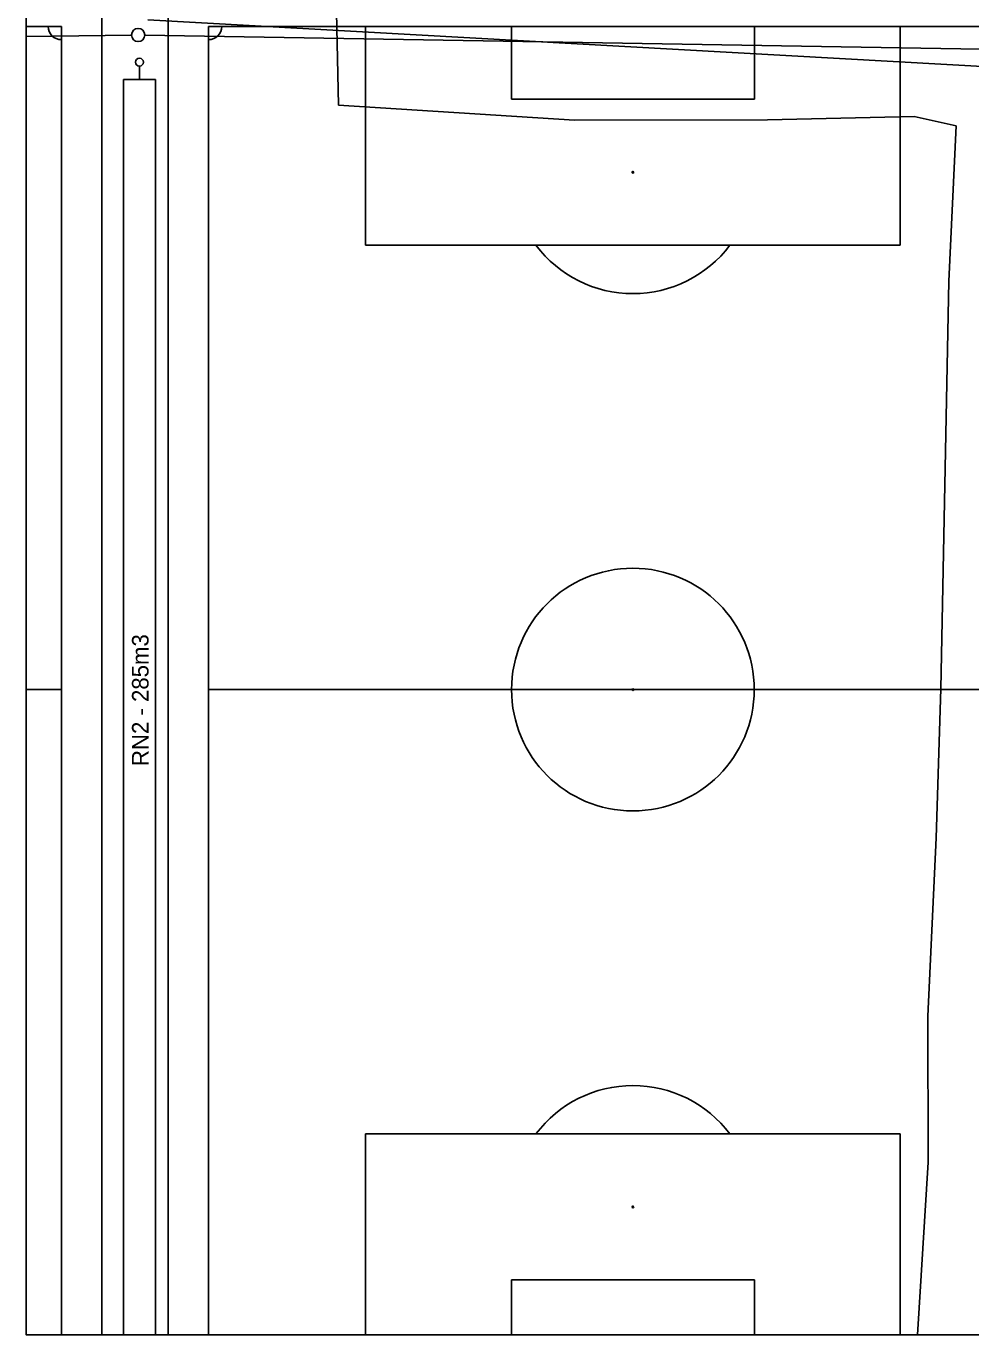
# Model space of a CAD drawing. Extents: x -264053 to -263843, y -1242290 to -1242141.
# Drawn here: x -264053.3 to -263982, y -1242289.6 to -1242191 of the extents above; entities that cross this region are included whole.
import ezdxf

# ---------------------------------------------------------------- set-up
doc = ezdxf.new("R2010")
doc.units = 0
for name, color, linetype in [('KFA_2D_JESTVUJUCE_IS_DSP', 7, 'Continuous'), ('KFA_2D_SITUACIA_DSP', 7, 'Continuous'), ('KFA_JESTV_IS_DSP', 7, 'Continuous'), ('KFA_SITUACIA_DSP', 7, 'Continuous'), ('RAM_NA_TLAC_A3_1-500', 7, 'Continuous')]:
    doc.layers.add(name, color=color, linetype=linetype)

msp = doc.modelspace()

# ---------------------------------------------------------------- linework, layer by layer
at = {"layer": 'KFA_2D_JESTVUJUCE_IS_DSP'}
for p, q in [((-264029.913, -1242188.318), (-264029.719, -1242196.934)), ((-263970.367, -1242194.605), (-264044.102, -1242190.483)), ((-264045.328, -1242191.64), (-264053.272, -1242191.755)), ((-263970.542, -1242192.875), (-264044.328, -1242191.641)), ((-264029.719, -1242196.934), (-264011.931, -1242198.062)), ((-264011.931, -1242198.062), (-263997.36, -1242198.031)), ((-263997.36, -1242198.031), (-263986.295, -1242197.77)), ((-263986.295, -1242197.77), (-263983.14, -1242198.474)), ((-263983.14, -1242198.474), (-263983.691, -1242210.183)), ((-263983.691, -1242210.183), (-263984.287, -1242240.935)), ((-263984.287, -1242240.935), (-263984.635, -1242252.165)), ((-263984.635, -1242252.165), (-263985.267, -1242265.602)), ((-263985.267, -1242265.602), (-263985.239, -1242276.615)), ((-263985.239, -1242276.615), (-263986.05, -1242289.625))]:
    msp.add_line(p, q, dxfattribs=at)
msp.add_circle((-264044.828, -1242191.633), 0.5, dxfattribs=at)
at = {"layer": 'KFA_2D_SITUACIA_DSP'}
for p, q in [((-264053.272, -1242289.625), (-264053.272, -1242187.932)), ((-264047.568, -1242187.932), (-264047.568, -1242289.625)), ((-264042.568, -1242187.932), (-264042.568, -1242289.625)), ((-264050.618, -1242190.982), (-264053.272, -1242190.982)), ((-264050.618, -1242289.625), (-264050.618, -1242190.982)), ((-263975.518, -1242190.982), (-264039.518, -1242190.982)), ((-264039.518, -1242190.982), (-264039.518, -1242289.625)), ((-264027.678, -1242207.482), (-264027.678, -1242190.982)), ((-264016.678, -1242190.982), (-264016.678, -1242196.482)), ((-263998.358, -1242196.482), (-263998.358, -1242190.982)), ((-263987.358, -1242190.982), (-263987.358, -1242207.482)), ((-264044.727, -1242194.982), (-264044.727, -1242193.982)), ((-264043.527, -1242194.982), (-264045.927, -1242194.982)), ((-264045.927, -1242194.982), (-264045.927, -1242289.625)), ((-264043.527, -1242289.625), (-264043.527, -1242194.982)), ((-264016.678, -1242196.482), (-263998.358, -1242196.482)), ((-263987.358, -1242207.482), (-264027.678, -1242207.482)), ((-264050.618, -1242240.982), (-264053.272, -1242240.982)), ((-263975.518, -1242240.982), (-264039.518, -1242240.982)), ((-263987.358, -1242274.482), (-264027.678, -1242274.482)), ((-264027.678, -1242274.482), (-264027.678, -1242289.625)), ((-263987.358, -1242289.625), (-263987.358, -1242274.482)), ((-264016.678, -1242289.625), (-264016.678, -1242285.482)), ((-264016.678, -1242285.482), (-263998.358, -1242285.482)), ((-263998.358, -1242285.482), (-263998.358, -1242289.625)), ((-264047.568, -1242289.625), (-264053.272, -1242289.625)), ((-264042.568, -1242289.625), (-263972.468, -1242289.625))]:
    msp.add_line(p, q, dxfattribs=at)
for centre, radius in [((-264044.727, -1242193.682), 0.3), ((-264007.518, -1242201.982), 0.06), ((-264007.518, -1242279.982), 0.06)]:
    msp.add_circle(centre, radius, dxfattribs=at)
for centre, radius, start, end in [((-264050.618, -1242190.982), 1, 180, 270), ((-264039.518, -1242190.982), 1, 270, 360), ((-264007.518, -1242201.982), 0.0303, 90, 270), ((-264007.518, -1242201.982), 0.0303, 270, 90), ((-264007.518, -1242201.982), 9.15, 216.94821, 323.05179), ((-264007.518, -1242240.982), 9.15, 360, 180), ((-264007.518, -1242240.982), 9.15, 180, 360), ((-264007.518, -1242240.982), 0.0605, 90, 270), ((-264007.518, -1242240.982), 0.0605, 270, 90), ((-264007.518, -1242279.982), 9.15, 36.94821, 143.05179), ((-264007.518, -1242279.982), 0.0303, 90, 270), ((-264007.518, -1242279.982), 0.0303, 270, 90)]:
    msp.add_arc(centre, radius, start, end, dxfattribs=at)
at = {"layer": 'KFA_JESTV_IS_DSP'}
for p, q in [((-263970.367, -1242194.605), (-264044.102, -1242190.483)), ((-264045.328, -1242191.64), (-264053.272, -1242191.755)), ((-263970.542, -1242192.875), (-264044.328, -1242191.641))]:
    msp.add_line(p, q, dxfattribs=at)
msp.add_circle((-264044.828, -1242191.633), 0.5, dxfattribs=at)
at = {"layer": 'KFA_SITUACIA_DSP'}
for p, q in [((-264053.272, -1242289.625), (-264053.272, -1242187.932)), ((-264047.568, -1242187.932), (-264047.568, -1242289.625)), ((-264042.568, -1242187.932), (-264042.568, -1242289.625)), ((-264050.618, -1242190.982), (-264053.272, -1242190.982)), ((-264050.618, -1242289.625), (-264050.618, -1242190.982)), ((-263975.518, -1242190.982), (-264039.518, -1242190.982)), ((-264039.518, -1242190.982), (-264039.518, -1242289.625)), ((-264027.678, -1242207.482), (-264027.678, -1242190.982)), ((-264016.678, -1242190.982), (-264016.678, -1242196.482)), ((-263998.358, -1242196.482), (-263998.358, -1242190.982)), ((-263987.358, -1242190.982), (-263987.358, -1242207.482)), ((-264044.727, -1242194.982), (-264044.727, -1242193.982)), ((-264043.527, -1242194.982), (-264045.927, -1242194.982)), ((-264045.927, -1242194.982), (-264045.927, -1242289.625)), ((-264043.527, -1242289.625), (-264043.527, -1242194.982)), ((-264016.678, -1242196.482), (-263998.358, -1242196.482)), ((-263987.358, -1242207.482), (-264027.678, -1242207.482)), ((-264050.618, -1242240.982), (-264053.272, -1242240.982)), ((-263975.518, -1242240.982), (-264039.518, -1242240.982)), ((-263987.358, -1242274.482), (-264027.678, -1242274.482)), ((-264027.678, -1242274.482), (-264027.678, -1242289.625)), ((-263987.358, -1242289.625), (-263987.358, -1242274.482)), ((-264016.678, -1242289.625), (-264016.678, -1242285.482)), ((-264016.678, -1242285.482), (-263998.358, -1242285.482)), ((-263998.358, -1242285.482), (-263998.358, -1242289.625)), ((-264047.568, -1242289.625), (-264053.272, -1242289.625)), ((-264042.568, -1242289.625), (-263972.468, -1242289.625))]:
    msp.add_line(p, q, dxfattribs=at)
for centre, radius in [((-264044.727, -1242193.682), 0.3), ((-264007.518, -1242201.982), 0.06), ((-264007.518, -1242279.982), 0.06)]:
    msp.add_circle(centre, radius, dxfattribs=at)
for centre, radius, start, end in [((-264050.618, -1242190.982), 1, 180, 270), ((-264039.518, -1242190.982), 1, 270, 360), ((-264007.518, -1242201.982), 0.0303, 90, 270), ((-264007.518, -1242201.982), 0.0303, 270, 90), ((-264007.518, -1242201.982), 9.15, 216.94821, 323.05179), ((-264007.518, -1242240.982), 9.15, 360, 180), ((-264007.518, -1242240.982), 9.15, 180, 360), ((-264007.518, -1242240.982), 0.0605, 90, 270), ((-264007.518, -1242240.982), 0.0605, 270, 90), ((-264007.518, -1242279.982), 9.15, 36.94821, 143.05179), ((-264007.518, -1242279.982), 0.0303, 90, 270), ((-264007.518, -1242279.982), 0.0303, 270, 90)]:
    msp.add_arc(centre, radius, start, end, dxfattribs=at)
at = {"layer": 'RAM_NA_TLAC_A3_1-500'}
msp.add_lwpolyline([(-264053.272, -1242141.125), (-263843.272, -1242141.125), (-263843.272, -1242289.625), (-264053.272, -1242289.625)], close=True, dxfattribs=at)

# ---------------------------------------------------------------- texts
at = {"layer": 'KFA_2D_SITUACIA_DSP'}
msp.add_text('RN2 - 285m3', height=1.25, rotation=90, dxfattribs=at).set_placement((-264044.042, -1242246.747))
at = {"layer": 'KFA_SITUACIA_DSP'}
msp.add_text('RN2 - 285m3', height=1.25, rotation=90, dxfattribs=at).set_placement((-264044.042, -1242246.747))

doc.saveas('drawing.dxf')
